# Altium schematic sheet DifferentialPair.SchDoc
size A2
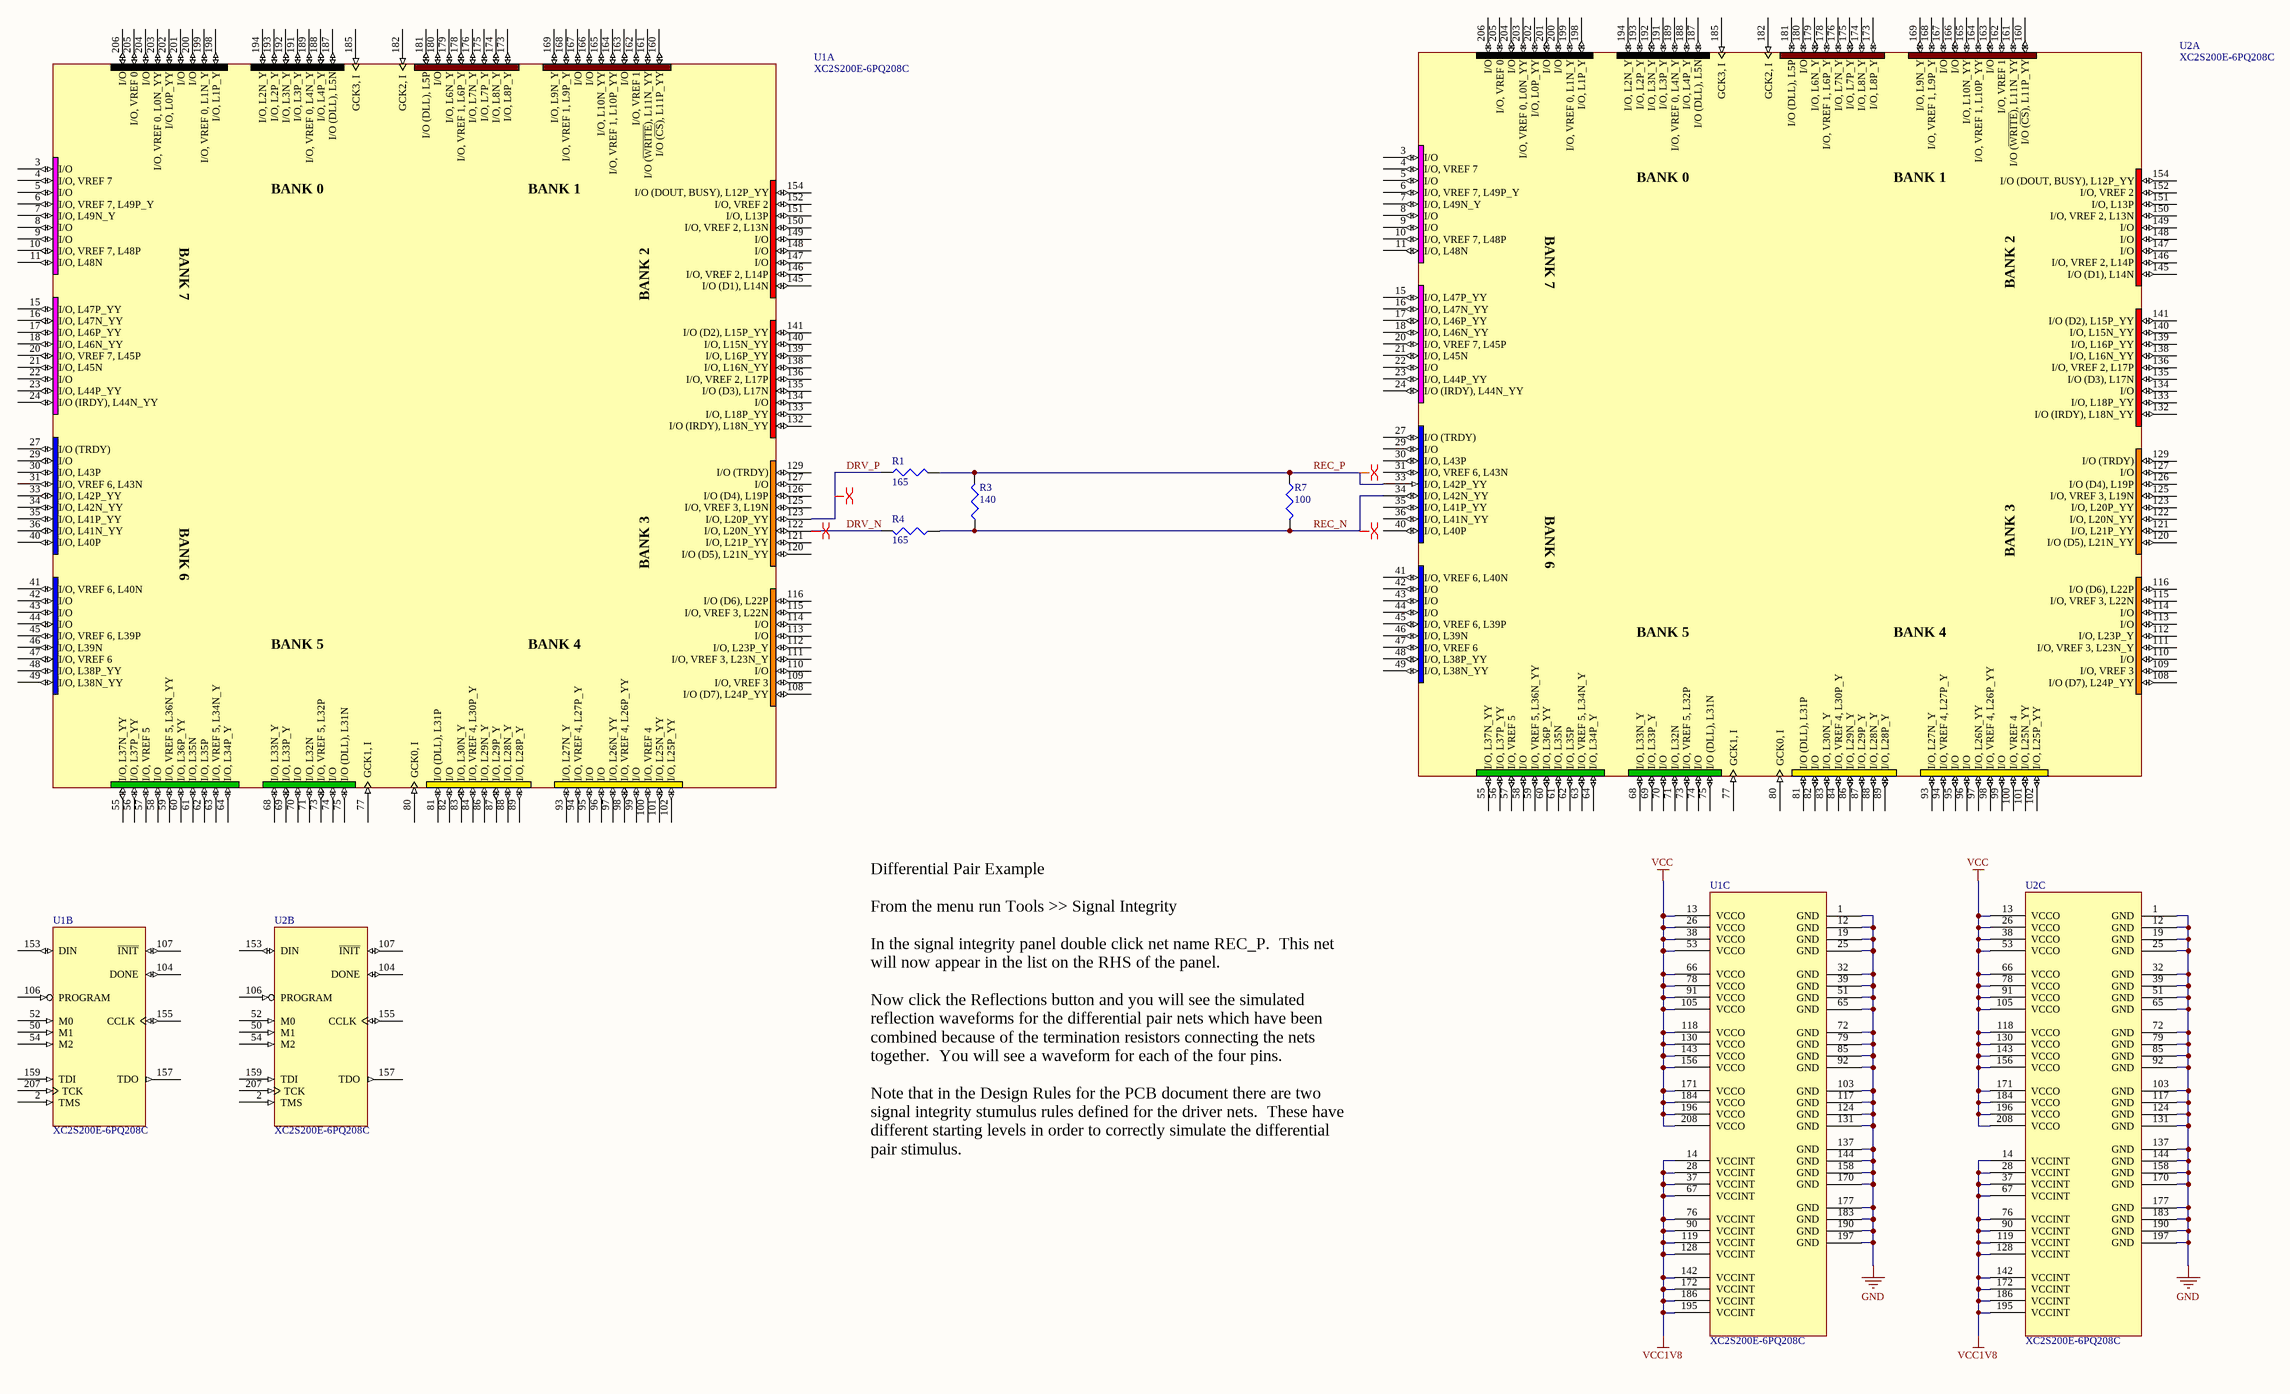
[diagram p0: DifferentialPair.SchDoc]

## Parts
R1  value 165  [J1-0603]  (hidden comment: Res3)
R3  value 140  [J1-0603]  (hidden comment: Res3)
R4  value 165  [J1-0603]  (hidden comment: Res3)
R7  value 100  [J1-0603]  (hidden comment: Res3)
U1  XC2S200E-6PQ208C  [PQ208]  (parts A,B,C of 3)
U2  XC2S200E-6PQ208C  [PQ208]  (parts A,B,C of 3)

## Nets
GND: U1.1(GND) U1.12(GND) U1.19(GND) U1.25(GND) U1.32(GND) U1.39(GND) U1.51(GND) U1.65(GND) U1.72(GND) U1.79(GND) U1.85(GND) U1.92(GND) U1.103(GND) U1.117(GND) U1.124(GND) U1.131(GND) U1.137(GND) U1.144(GND) U1.158(GND) U1.170(GND) U1.177(GND) U1.183(GND) U1.190(GND) U1.197(GND) U2.1(GND) U2.12(GND) U2.19(GND) U2.25(GND) U2.32(GND) U2.39(GND) U2.51(GND) U2.65(GND) U2.72(GND) U2.79(GND) U2.85(GND) U2.92(GND) U2.103(GND) U2.117(GND) U2.124(GND) U2.131(GND) U2.137(GND) U2.144(GND) U2.158(GND) U2.170(GND) U2.177(GND) U2.183(GND) U2.190(GND) U2.197(GND)
VCC: U1.13(VCCO) U1.26(VCCO) U1.38(VCCO) U1.53(VCCO) U1.66(VCCO) U1.78(VCCO) U1.91(VCCO) U1.105(VCCO) U1.118(VCCO) U1.130(VCCO) U1.143(VCCO) U1.156(VCCO) U1.171(VCCO) U1.184(VCCO) U1.196(VCCO) U1.208(VCCO) U2.13(VCCO) U2.26(VCCO) U2.38(VCCO) U2.53(VCCO) U2.66(VCCO) U2.78(VCCO) U2.91(VCCO) U2.105(VCCO) U2.118(VCCO) U2.130(VCCO) U2.143(VCCO) U2.156(VCCO) U2.171(VCCO) U2.184(VCCO) U2.196(VCCO) U2.208(VCCO)
VCC1V8: U1.14(VCCINT) U1.28(VCCINT) U1.37(VCCINT) U1.67(VCCINT) U1.76(VCCINT) U1.90(VCCINT) U1.119(VCCINT) U1.128(VCCINT) U1.142(VCCINT) U1.172(VCCINT) U1.186(VCCINT) U1.195(VCCINT) U2.14(VCCINT) U2.28(VCCINT) U2.37(VCCINT) U2.67(VCCINT) U2.76(VCCINT) U2.90(VCCINT) U2.119(VCCINT) U2.128(VCCINT) U2.142(VCCINT) U2.172(VCCINT) U2.186(VCCINT) U2.195(VCCINT)
DRV_N: R4.2 U1.122(I/O,_L20N_YY)
DRV_P: R1.1 U1.123(I/O,_L20P_YY)
REC_N: R3.1 R4.1 R7.2 U2.34(I/O,_L42N_YY)
REC_P: R1.2 R3.2 R7.1 U2.33(I/O,_L42P_YY)

Not connected (* = marked no-connect by the designer): U1 2(TMS) 3(I/O) 4(I/O,_VREF_7) 5(I/O) 6(I/O,_VREF_7,_L49P_Y) 7(I/O,_L49N_Y) 8(I/O) 9(I/O) 10(I/O,_VREF_7,_L48P) 11(I/O,_L48N) 15(I/O,_L47P_YY) 16(I/O,_L47N_YY) 17(I/O,_L46P_YY) 18(I/O,_L46N_YY) 20(I/O,_VREF_7,_L45P) 21(I/O,_L45N) 22(I/O) 23(I/O,_L44P_YY) 24(I/O_(IRDY),_L44N_YY) 27(I/O_(TRDY)) 29(I/O) 30(I/O,_L43P) 31(I/O,_VREF_6,_L43N) 33(I/O,_L42P_YY) 34(I/O,_L42N_YY) 35(I/O,_L41P_YY) 36(I/O,_L41N_YY) 40(I/O,_L40P) 41(I/O,_VREF_6,_L40N) 42(I/O) 43(I/O) 44(I/O) 45(I/O,_VREF_6,_L39P) 46(I/O,_L39N) 47(I/O,_VREF_6) 48(I/O,_L38P_YY) 49(I/O,_L38N_YY) 50(M1) 52(M0) 54(M2) 55(I/O,_L37N_YY) 56(I/O,_L37P_YY) 57(I/O,_VREF_5) 58(I/O) 59(I/O,_VREF_5,_L36N_YY) 60(I/O,_L36P_YY) 61(I/O,_L35N) 62(I/O,_L35P) 63(I/O,_VREF_5,_L34N_Y) 64(I/O,_L34P_Y) 68(I/O,_L33N_Y) 69(I/O,_L33P_Y) 70(I/O) 71(I/O,_L32N) 73(I/O,_VREF_5,_L32P) 74(I/O) 75(I/O_(DLL),_L31N) 77(GCK1,_I) 80(GCK0,_I) 81(I/O_(DLL),_L31P) 82(I/O) 83(I/O,_L30N_Y) 84(I/O,_VREF_4,_L30P_Y) 86(I/O,_L29N_Y) 87(I/O,_L29P_Y) 88(I/O,_L28N_Y) 89(I/O,_L28P_Y) 93(I/O,_L27N_Y) 94(I/O,_VREF_4,_L27P_Y) 95(I/O) 96(I/O) 97(I/O,_L26N_YY) 98(I/O,_VREF_4,_L26P_YY) 99(I/O) 100(I/O,_VREF_4) 101(I/O,_L25N_YY) 102(I/O,_L25P_YY) 104(DONE) 106(PROGRAM) 107(~{INIT}) 108(I/O_(D7),_L24P_YY) 109(I/O,_VREF_3) 110(I/O) 111(I/O,_VREF_3,_L23N_Y) 112(I/O,_L23P_Y) 113(I/O) 114(I/O) 115(I/O,_VREF_3,_L22N) 116(I/O_(D6),_L22P) 120(I/O_(D5),_L21N_YY) 121(I/O,_L21P_YY) 125(I/O,_VREF_3,_L19N) 126(I/O_(D4),_L19P) 127(I/O) 129(I/O_(TRDY)) 132(I/O_(IRDY),_L18N_YY) 133(I/O,_L18P_YY) 134(I/O) 135(I/O_(D3),_L17N) 136(I/O,_VREF_2,_L17P) 138(I/O,_L16N_YY) 139(I/O,_L16P_YY) 140(I/O,_L15N_YY) 141(I/O_(D2),_L15P_YY) 145(I/O_(D1),_L14N) 146(I/O,_VREF_2,_L14P) 147(I/O) 148(I/O) 149(I/O) 150(I/O,_VREF_2,_L13N) 151(I/O,_L13P) 152(I/O,_VREF_2) 153(DIN) 154(I/O_(DOUT,_BUSY),_L12P_YY) 155(CCLK) 157(TDO) 159(TDI) 160(I/O_(~{CS}),_L11P_YY) 161(I/O_(~{WRITE}),_L11N_YY) 162(I/O,_VREF_1) 163(I/O) 164(I/O,_VREF_1,_L10P_YY) 165(I/O,_L10N_YY) 166(I/O) 167(I/O) 168(I/O,_VREF_1,_L9P_Y) 169(I/O,_L9N_Y) 173(I/O,_L8P_Y) 174(I/O,_L8N_Y) 175(I/O,_L7P_Y) 176(I/O,_L7N_Y) 178(I/O,_VREF_1,_L6P_Y) 179(I/O,_L6N_Y) 180(I/O) 181(I/O_(DLL),_L5P) 182(GCK2,_I) 185(GCK3,_I) 187(I/O_(DLL),_L5N) 188(I/O,_L4P_Y) 189(I/O,_VREF_0,_L4N_Y) 191(I/O,_L3P_Y) 192(I/O,_L3N_Y) 193(I/O,_L2P_Y) 194(I/O,_L2N_Y) 198(I/O,_L1P_Y) 199(I/O,_VREF_0,_L1N_Y) 200(I/O) 201(I/O) 202(I/O,_L0P_YY) 203(I/O,_VREF_0,_L0N_YY) 204(I/O) 205(I/O,_VREF_0) 206(I/O) 207(TCK); U2 2(TMS) 3(I/O) 4(I/O,_VREF_7) 5(I/O) 6(I/O,_VREF_7,_L49P_Y) 7(I/O,_L49N_Y) 8(I/O) 9(I/O) 10(I/O,_VREF_7,_L48P) 11(I/O,_L48N) 15(I/O,_L47P_YY) 16(I/O,_L47N_YY) 17(I/O,_L46P_YY) 18(I/O,_L46N_YY) 20(I/O,_VREF_7,_L45P) 21(I/O,_L45N) 22(I/O) 23(I/O,_L44P_YY) 24(I/O_(IRDY),_L44N_YY) 27(I/O_(TRDY)) 29(I/O) 30(I/O,_L43P) 31(I/O,_VREF_6,_L43N) 35(I/O,_L41P_YY) 36(I/O,_L41N_YY) 40(I/O,_L40P) 41(I/O,_VREF_6,_L40N) 42(I/O) 43(I/O) 44(I/O) 45(I/O,_VREF_6,_L39P) 46(I/O,_L39N) 47(I/O,_VREF_6) 48(I/O,_L38P_YY) 49(I/O,_L38N_YY) 50(M1) 52(M0) 54(M2) 55(I/O,_L37N_YY) 56(I/O,_L37P_YY) 57(I/O,_VREF_5) 58(I/O) 59(I/O,_VREF_5,_L36N_YY) 60(I/O,_L36P_YY) 61(I/O,_L35N) 62(I/O,_L35P) 63(I/O,_VREF_5,_L34N_Y) 64(I/O,_L34P_Y) 68(I/O,_L33N_Y) 69(I/O,_L33P_Y) 70(I/O) 71(I/O,_L32N) 73(I/O,_VREF_5,_L32P) 74(I/O) 75(I/O_(DLL),_L31N) 77(GCK1,_I) 80(GCK0,_I) 81(I/O_(DLL),_L31P) 82(I/O) 83(I/O,_L30N_Y) 84(I/O,_VREF_4,_L30P_Y) 86(I/O,_L29N_Y) 87(I/O,_L29P_Y) 88(I/O,_L28N_Y) 89(I/O,_L28P_Y) 93(I/O,_L27N_Y) 94(I/O,_VREF_4,_L27P_Y) 95(I/O) 96(I/O) 97(I/O,_L26N_YY) 98(I/O,_VREF_4,_L26P_YY) 99(I/O) 100(I/O,_VREF_4) 101(I/O,_L25N_YY) 102(I/O,_L25P_YY) 104(DONE) 106(PROGRAM) 107(~{INIT}) 108(I/O_(D7),_L24P_YY) 109(I/O,_VREF_3) 110(I/O) 111(I/O,_VREF_3,_L23N_Y) 112(I/O,_L23P_Y) 113(I/O) 114(I/O) 115(I/O,_VREF_3,_L22N) 116(I/O_(D6),_L22P) 120(I/O_(D5),_L21N_YY) 121(I/O,_L21P_YY) 122(I/O,_L20N_YY) 123(I/O,_L20P_YY) 125(I/O,_VREF_3,_L19N) 126(I/O_(D4),_L19P) 127(I/O) 129(I/O_(TRDY)) 132(I/O_(IRDY),_L18N_YY) 133(I/O,_L18P_YY) 134(I/O) 135(I/O_(D3),_L17N) 136(I/O,_VREF_2,_L17P) 138(I/O,_L16N_YY) 139(I/O,_L16P_YY) 140(I/O,_L15N_YY) 141(I/O_(D2),_L15P_YY) 145(I/O_(D1),_L14N) 146(I/O,_VREF_2,_L14P) 147(I/O) 148(I/O) 149(I/O) 150(I/O,_VREF_2,_L13N) 151(I/O,_L13P) 152(I/O,_VREF_2) 153(DIN) 154(I/O_(DOUT,_BUSY),_L12P_YY) 155(CCLK) 157(TDO) 159(TDI) 160(I/O_(~{CS}),_L11P_YY) 161(I/O_(~{WRITE}),_L11N_YY) 162(I/O,_VREF_1) 163(I/O) 164(I/O,_VREF_1,_L10P_YY) 165(I/O,_L10N_YY) 166(I/O) 167(I/O) 168(I/O,_VREF_1,_L9P_Y) 169(I/O,_L9N_Y) 173(I/O,_L8P_Y) 174(I/O,_L8N_Y) 175(I/O,_L7P_Y) 176(I/O,_L7N_Y) 178(I/O,_VREF_1,_L6P_Y) 179(I/O,_L6N_Y) 180(I/O) 181(I/O_(DLL),_L5P) 182(GCK2,_I) 185(GCK3,_I) 187(I/O_(DLL),_L5N) 188(I/O,_L4P_Y) 189(I/O,_VREF_0,_L4N_Y) 191(I/O,_L3P_Y) 192(I/O,_L3N_Y) 193(I/O,_L2P_Y) 194(I/O,_L2N_Y) 198(I/O,_L1P_Y) 199(I/O,_VREF_0,_L1N_Y) 200(I/O) 201(I/O) 202(I/O,_L0P_YY) 203(I/O,_VREF_0,_L0N_YY) 204(I/O) 205(I/O,_VREF_0) 206(I/O) 207(TCK)

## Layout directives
differential pair: DRV_N, DRV_P, REC_N, REC_P

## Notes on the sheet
- Differential Pair Example
  From the menu run Tools >> Signal Integrity
  In the signal integrity panel double click net name REC_P.  This net will now appear in the list on the RHS of the panel.
  Now click the Reflections button and you will see the simulated reflection waveforms for the differential pair nets which have been combined because of the termination resistors connecting the nets together.  You will see a waveform for each of the four pins.
  Note that in the Design Rules for the PCB document there are two signal integrity stumulus rules defined for the driver nets.  These have different starting levels in order to correctly simulate the differential pair stimulus.

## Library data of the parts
R1 R3 R4 R7 = Res3: Resistor
U1 U2 = XC2S200E-6PQ208C: Spartan-IIE 1.8V FPGA, 208-Pin PQFP, Standard Performance, Commercial Grade; Package Information: Latest Revision: ver1.1, Oct-2002; Code - JEDEC: MS-029-FA-1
